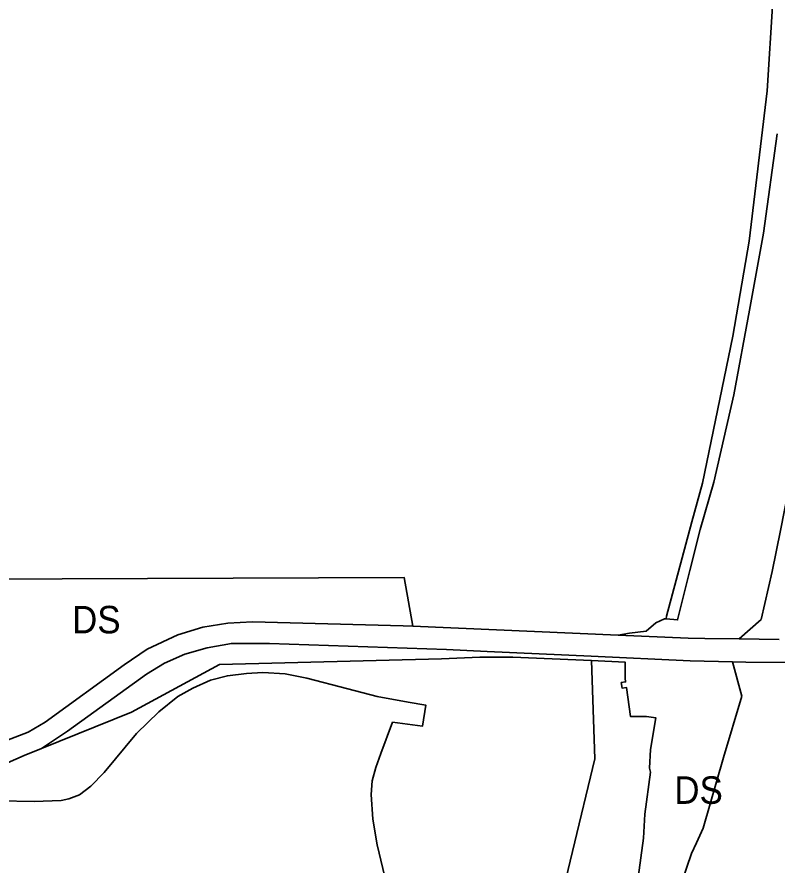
# Model space of a CAD drawing. Extents: x -650451 to -642268, y -1075216 to -1066610.
# Drawn here: x -645413.5 to -644999, y -1070883.4 to -1070420.9 of the extents above; entities that cross this region are included whole.
import ezdxf

# ---------------------------------------------------------------- set-up
doc = ezdxf.new("R2010")
doc.units = 0
doc.header["$LTSCALE"] = 6
doc.layers.add('1', color=7, linetype='Continuous', lineweight=35)
doc.layers.add('3', color=7, linetype='Continuous')

msp = doc.modelspace()

# ---------------------------------------------------------------- linework, layer by layer
at = {"layer": '1'}
for p, q in [((-645085.58, -1070758.04), (-645047.39, -1070759.71)), ((-645019.57, -1070760.07), (-644997.82, -1070760.38)), ((-645156.988, -1070766.884), (-645100.32, -1070769.5)), ((-645100.32, -1070769.5), (-645046.46, -1070771.98)), ((-645046.46, -1070771.98), (-645023.25, -1070772.62)), ((-645016.08, -1070772.8), (-645023.25, -1070772.62)), ((-645016.08, -1070772.8), (-644994.64, -1070772.97))]:
    msp.add_line(p, q, dxfattribs=at)
for points in [[(-644970.61, -1070323.44), (-644971.37, -1070345.98), (-644972.48, -1070389.15), (-644974.69, -1070427.86), (-644975.29, -1070440.14), (-644974.44, -1070482.48), (-644975.05, -1070536.16), (-644978.44, -1070578.56), (-644985.04, -1070633.43), (-644992.6, -1070677.92), (-644997.14, -1070700.88), (-645001.71, -1070723.39), (-645007.68, -1070749.5), (-645019.57, -1070760.07)], [(-645004.523, -1070326.697), (-645004.434, -1070327.302), (-645001.312, -1070412.099), (-645004.327, -1070461.264), (-645014.277, -1070543.11), (-645023.048, -1070595.033), (-645039.574, -1070675.065), (-645045.493, -1070696.321), (-645059.308, -1070747.712), (-645059.403, -1070749.195)], [(-645059.403, -1070749.195), (-645053.21, -1070749.75), (-645046.63, -1070722.77), (-645041, -1070700.44), (-645033.53, -1070674.55), (-645022.64, -1070626.93), (-645014.07, -1070580.72), (-645006.44, -1070538.78), (-644998.92, -1070484.58)], [(-645435.711, -1070727.497), (-645202.41, -1070726.571), (-645197.539, -1070753.128)], [(-645202.96, -1070752.89), (-645285.11, -1070750.69), (-645298.41, -1070751.48), (-645312.2, -1070753.77), (-645325.82, -1070757.94), (-645342.41, -1070765.76), (-645354.98, -1070774.28), (-645398.04, -1070805.44), (-645407.37, -1070810.95), (-645419.18, -1070815.44), (-645432.07, -1070816.05), (-645445.81, -1070814.06)], [(-645085.58, -1070758.04), (-645079.38, -1070756.91), (-645070.3, -1070755.92), (-645065.17, -1070751.39), (-645060.46, -1070749.1), (-645059.403, -1070749.195)], [(-645085.58, -1070758.04), (-645197.539, -1070753.128), (-645202.96, -1070752.89)], [(-645019.57, -1070760.07), (-645038.44, -1070759.83), (-645047.39, -1070759.71)], [(-645156.988, -1070766.884), (-645179.18, -1070765.86), (-645275.8, -1070762.66), (-645296.51, -1070762.52), (-645309.78, -1070764.88), (-645321.9, -1070768.47), (-645333.12, -1070773.33), (-645342.94, -1070779.31), (-645385.99, -1070810.35), (-645400.05, -1070819.84)], [(-645303, -1070774), (-645182, -1070771), (-645161, -1070770), (-645143, -1070770), (-645100.268, -1070771.946)], [(-645400.05, -1070819.84), (-645351, -1070800), (-645303, -1070774)], [(-645134.973, -1070977.077), (-645098.438, -1070825.558), (-645100.268, -1070771.946)], [(-645100.268, -1070771.946), (-645081.75, -1070772.79), (-645081.85, -1070781.59), (-645081.57, -1070783.53), (-645083.95, -1070783.89), (-645083.49, -1070786.92), (-645081.13, -1070786.56), (-645078.85, -1070802.46), (-645070.2, -1070802.33), (-645065.01, -1070803.22), (-645068.07, -1070820.37), (-645068.52, -1070830.52), (-645068.07, -1070832.72), (-645071.18, -1070855.63), (-645071.77, -1070868.73), (-645078.23, -1070915.65), (-645092.67, -1070979.52)], [(-645023.25, -1070772.62), (-645018.18, -1070791.34), (-645028.25, -1070824.83), (-645039.25, -1070863.33), (-645043, -1070871.35), (-645045.74, -1070877.19), (-645050.47, -1070891.48), (-645064.39, -1070944.7), (-645071.99, -1070980.72)], [(-645206.872, -1070914.991), (-645216.991, -1070872.38), (-645219.351, -1070858.481), (-645220.312, -1070845.02), (-645219.787, -1070837.502), (-645217.778, -1070830.159), (-645215.063, -1070822.589), (-645208.696, -1070805.535), (-645192.298, -1070807.665), (-645190.59, -1070796.152), (-645200.111, -1070794.621), (-645217.086, -1070791.58), (-645233.003, -1070787.399), (-645255.407, -1070781.443), (-645267.315, -1070779.162), (-645279.349, -1070778.402), (-645288.343, -1070778.909), (-645298.731, -1070780.176), (-645307.923, -1070782.557), (-645317.677, -1070786.866), (-645325.785, -1070791.428), (-645336.046, -1070799.793), (-645348.318, -1070811.675), (-645366.02, -1070832.94), (-645373.241, -1070840.417), (-645379.448, -1070845.106), (-645385.148, -1070847.387), (-645389.329, -1070848.148), (-645404.15, -1070848.781), (-645423.364, -1070848.402)], [(-645642.52, -1070788.7), (-645625, -1070793.5), (-645610.25, -1070797.55), (-645558.3, -1070808), (-645494.82, -1070818.45), (-645452.31, -1070825.52), (-645433.49, -1070828.76), (-645418.67, -1070827.72), (-645409.52, -1070823.76), (-645400.05, -1070819.84)]]:
    msp.add_lwpolyline(points, dxfattribs=at)

# ---------------------------------------------------------------- texts
at = {"layer": '3', "width": 0.95}
for p in [(-645383.453, -1070757.076), (-645055.027, -1070850.038)]:
    msp.add_text('DS', height=15, dxfattribs=at).set_placement(p)

doc.saveas('drawing.dxf')
